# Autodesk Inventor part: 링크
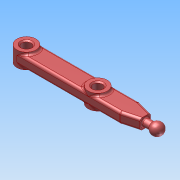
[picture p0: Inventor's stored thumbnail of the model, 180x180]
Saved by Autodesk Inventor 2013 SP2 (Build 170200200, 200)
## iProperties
Created: 2025-07
Part Number: 링크
Material: Generic
Document SubType Name: Modeling
Designer: a
Density: 1 g/cm^3
Author: a
변환 표준: STEP AP214IS
전처리기: Build: 200, Release: 2013 SP2 Update 6 - Date: Thu 07/17/2014
전송 단위: 밀리미터
불확실성: 0.01
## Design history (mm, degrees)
node "링크1"
node "솔리드1"
node "기준1"
